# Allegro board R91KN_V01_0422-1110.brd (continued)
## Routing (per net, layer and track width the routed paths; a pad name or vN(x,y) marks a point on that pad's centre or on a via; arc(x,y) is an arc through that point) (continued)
+3.3V_DPB:
  vias: v3(13.55,88.3) v3(13.9,90.9) v3(14.45,88.4) v3(14.65,90.9)
+5V: length 43.7
  TOP w1: v2(36.37,40.31) 43.96,47.9 v2(43.97,47.9) ; v2(48.49,30.4) 42.55,30.4 v2(42.52,30.38) 40.24,28.1 R4413.1
  BOTTOM w1: v2(36.37,40.31) 36.37,36.53 v2(42.52,30.38) ; U861.4 50.18,26.49 48.76,26.49 C868.1 48.08,26.71 47.2,27.58 47.2,29.12 v2(48.49,30.4) 48.54,30.45 48.54,30.5 48.55,30.51 R866.1
+5V_HDMI: length 48.9
  TOP w0.3: C2722.1 16.06,60.7 13.02,60.7 11.73,59.41 MJ2501.18
  TOP w0.5: v3(19.85,61.54) 18.89,61.54 17.95,60.6 17.35,60.6 16.96,60.21 C2722.1 ; v3(19.85,60.24) R2701.1
  TOP w0.7: v3(19.85,61.54) R2703.1
  L3_INNER w1: v3(35.35,33.7) 35.35,36.9 22.86,49.39 22.86,57.23 v3(19.85,60.24) v3(19.85,61.54)
  BOTTOM w0.7: MR2721.2 34.88,34.17 v3(35.35,33.7)
+5V_VESA: length 57.6
  TOP w0.7: v3(18.18,22.5) R1005.1 17.34,22.09 ; R1008.1 v3(18.21,23.8)
  TOP w1: v3(13.85,21.4) 14.05,21.2 16.45,21.2 17.34,22.09 ; R4412.1 37.94,27.51 v3(37.95,27.5)
  L3_INNER w1: v3(18.18,22.5) 18.21,22.53 v3(18.21,23.8) 19.35,24.94 19.35,29.2 20.84,30.69 v3(20.84,32.51)
  BOTTOM w0.2: 10.46,23.88 9.52,24.82 7.75,24.82 6.84,23.91 J1601.14 7.82,22.91 9.5,22.91 10.46,23.88
  BOTTOM w0.7: 32,31.2 32.4,31.59 U1999.14 33.17,32.87
  BOTTOM w1: v3(13.85,21.4) 13.85,23.73 12.85,24.73 11.31,24.73 10.46,23.88 ; 33.17,32.87 R2014.1 33.47,33.17 R2721.1 34.58,32.77 37.95,29.4 v3(37.95,27.5) ; v3(20.84,32.51) C1624.1 26.13,32.51 C1999.2 26.8,32.55 28.15,31.2 32,31.2
+5V_VESA2: length 14.8
  TOP w1: R4411.1 v3(42.54,28.11)
  BOTTOM w0.5: 34.56,35.13 MR2721.1
  BOTTOM w0.7: MR2721.1 35.5,35.15 ; MR2014.1 34.56,35.13
  BOTTOM w1: 35.5,35.15 v3(42.54,28.11)
+5V_VGAH: length 95.1
  TOP w0.5: v3(19.04,91.49) R2008.1 ; 9.21,93.32 C1011.1 ; R2005.1 19.04,89.39 v3(18.45,88.8)
  TOP w1: 9.21,93.32 9.7,93.81 9.7,98.55 10.85,99.7 13.75,99.7 19.04,94.41 v3(19.04,91.49)
  L3_INNER w1: MJ1001.9 5.58,85.17 7.45,83.3 7.45,74.7 9.05,73.1 9.05,72.1 10.25,70.9 15.35,70.9 17.55,68.7 17.55,50.89 31.63,36.81 31.63,36.42 v3(32.25,35.8)
  BOTTOM w0.7: 32.25,34.69 32.8,34.15 MR2014.2
  BOTTOM w1: v3(18.45,88.8) 19.04,89.39 v3(19.04,91.49) ; v3(32.25,35.8) 32.25,34.69
  vias: v3(6.1,92.35) v3(7.25,92.4) v3(8.38,92.33)
+12V_BUS: length 52.4
  TOP w0.5: MPCIE1.B1 45.65,5.8 v2(46.85,7) ; C43.1 v3(114.55,107.9) ; v3(26.85,84.2) 31.44,84.2 R1805.1 ; R844.1 19.12,48.49 20.85,46.76 24.11,46.76 v3(27.45,50.1) ; C47.1 v3(152.05,105.1) ; R843.2 v3(150.95,105.1) ; R4055.2 v3(111.52,107.87) ; C44.1 v3(108.03,107.12) ; R4105.1 v3(156.75,30.9)
  TOP w0.8: D701.2 151.47,96.9 C706.1 152.06,97.11 v2(152.95,98) ; R707.1 v2(149.95,106.81) ; R607.1 65.61,96.44 65.15,96.9 v2(63.65,96.9) ; D601.2 59.96,106.33 C606.1 59.96,107.82 v2(60.68,108.53)
  BOTTOM w0.5: R1804.1 26.21,86.51 v3(26.59,86.89) ; R857.1 R852.2 v3(21.38,84.27)
  BOTTOM w0.8: v2(63.65,96.9) 62.51,96.9 58.9,100.51 58.9,104.04 v2(57.05,105.89)
  vias: v2(21.15,99.1) v2(21.15,97.5) v2(21.15,96.1) v2(21.35,104.6) v2(21.35,103.1) v2(25.25,106) v2(26.55,106.1) v2(46.75,11.6) v2(46.75,10.3) v2(46.75,9) v2(48.05,11.6) v2(48.05,10.3) v2(48.05,9) v2(48.05,7.7) v2(49.35,11.6) v2(49.35,10.3) v2(49.35,9) v2(50.65,11.6) v2(50.65,10.3) v2(50.65,9) v2(129.95,103.3) v2(131.15,103.3) v2(132.35,103.3) v3(160.55,31.1) v3(160.55,30.3) v3(161.45,31.1) v3(161.45,30.3)
+AVDD: length 4.2
  TOP w0.3: v1(81.35,52.65) 81.4,52.65 U1.AG24
  BOTTOM w0.4: C1054.1 80.29,51.67 C1055.1 79.27,51.02 78.79,50.53 B2.2
  BOTTOM w0.5: v1(81.35,52.65) 81.16,52.65 80.29,51.78 C1054.1
+VCCT_DAC: length 3.7
  TOP w0.25: U4050.13 64.36,89.45 63.99,89.45 63.77,89.23 63.27,89.23 R4075.2 ; C4070.1 62.54,89.99 63.26,89.27 R4075.2 ; C4071.1 R4075.2
+VDD1DI: length 12.9
  TOP w0.2: v3(77.85,53.14) 78.13,53.42 78.13,53.42 78.22,53.52 79.06,53.52 79.16,53.42 80.87,53.42 81.4,53.94 81.4,53.95 81.6,54.15 81.61,54.15 82.85,54.15 83.21,53.8 U1.AE23
  BOTTOM w0.4: v3(77.85,53.14) 78.54,53.83 78.9,53.83 79.32,53.41 C1052.1
  BOTTOM w0.5: v3(77.85,53.14) 76.28,53.14 C1050.1 76.14,51.89 B6.2 ; C1051.1 80.28,53.35 C1052.1
+VDDC: length 284.5
  TOP w0.3: U1.T12 89.75,61.6 U1.U13 89.75,61.3 v1(90.15,60.9) 90.55,60.5 U1.T15 v1(91.05,59.9) U1.R16 91.63,59.4 v1(92.04,59) 92.43,58.6 U1.N17 92.55,58.5 v1(92.97,58.08) ; U1.T12 90.55,62.38 v1(91.07,61.85) 91.1,61.85 U1.R13 91.55,61.34 v1(92.04,60.84) 92.48,60.4 U1.N15 ; U1.T12 90.55,62.52 v1(90.16,62.91) ; v1(92.97,59.87) 93.44,59.4 U1.M16 ; v1(92.97,59.87) 93.5,60.4 U1.M15 ; v1(92.97,59.87) 92.55,60.29 U1.N15 ; U1.N15 92.55,60.42 v1(93.09,60.97) 93.53,61.4 U1.M13 ; v1(87.24,61) 86.75,60.51 U1.AA15 U1.Y16 87.84,59.4 v1(88.25,58.99) 88.64,58.6 U1.V17 v1(89.25,58.1) U1.U18 89.75,57.5 v1(90.15,57.1) 90.55,56.7 U1.T20 90.55,56.55 91,56.1 91.05,56.1 U1.R21 ; 88.25,57.1 88.25,57.09 U1.Y18 ; 88.25,57.1 v1(88.25,57.16) ; 88.25,57.1 88.75,56.6 U1.V20 88.75,56.58 89.72,55.6 U1.U21 ; U1.Y21 87.75,55.65 NS600.1 88.72,55.6 U1.V21 ; U1.Y13 v3(88.25,60.9) U1.V15 v3(89.25,59.9) U1.U16 U1.T17 v1(91.05,58.1) U1.R18 91.55,57.55 v1(92,57.1) 92.5,56.6 U1.N20 92.56,56.6 v1(93.02,57.06) ; v1(93.02,57.06) 93.47,56.6 U1.M20 U1.M21 ; v1(93.02,57.06) 93.55,57.59 U1.M18 93.45,57.6 v1(92.97,58.08) ; v1(92.97,58.08) 93.5,58.6 U1.M17
  TOP w0.4: U1.M13 U1.M12 v1(93.05,62.9) U1.M11
  TOP w0.5: R841.1 143.62,105.45 v3(143.62,104.74)
  TOP w0.503: 53.54,89.9 L601.2 ; L601.2 52.11,90.43 ; L601.2 51.59,91.86 ; L601.2 53.54,93.81 ; L601.2 52.11,93.29 ; L601.2 54.97,93.29 ; L601.2 54.97,90.43 ; L601.2 55.49,91.86 ; C626.1 53.15,87.24 ; C626.1 53.15,86.68 ; C626.1 52.02,87.24 ; C626.1 53.15,86.11 ; C626.1 50.89,85.55 ; C626.1 52.58,87.24 ; C626.1 50.89,86.11 ; C626.1 50.89,87.24 ; C625.1 44.4,87.24 ; C625.1 44.96,87.24 ; C625.1 45.53,86.68 ; C625.1 45.53,86.11 ; C625.1 43.27,85.55 ; C625.1 43.27,86.11 ; C625.1 43.27,87.24 ; C625.1 45.53,87.24
  L3_INNER w0.5: NS600.1 89.1,56.11
  L3_INNER w0.603: 43.32,86.11 C625.1 ; C625.1 45.48,86.11 ; C625.1 44.4,87.19 ; C625.1 43.59,86.92 ; C625.1 45.21,85.3 ; C625.1 43.59,85.3 ; C625.1 44.4,85.04 ; C625.1 45.21,86.92 ; L601.2 53.54,93.76 ; L601.2 54.94,93.25 ; L601.2 53.54,89.95 ; L601.2 51.64,91.86 ; L601.2 54.94,90.46 ; L601.2 52.15,93.25 ; L601.2 55.44,91.86 ; L601.2 52.15,90.46 ; C626.1 52.83,86.92 ; C626.1 51.21,85.3 ; C626.1 52.02,85.04 ; C626.1 52.83,85.3 ; C626.1 51.21,86.92 ; C626.1 53.1,86.11 ; C626.1 52.02,87.19 ; C626.1 50.94,86.11
  BOTTOM w0.2: C172.1 94.57,56.58 C193.1
  BOTTOM w0.3: v1(90.16,62.91) 90.64,62.43 C190.1 ; v3(95.05,71.98) 95.05,71.3 95.67,70.68 95.67,70.12 MB9.1 ; C184.1 94.5,59.36 93.67,59.36 C189.1 93.45,59.35 93.1,59.01 v1(93.06,59.01) ; C195.1 91.57,61.31 v1(92.04,60.84) 92.26,60.84 C87.1 ; 87.29,59.99 C174.1 87.19,60.95 v1(87.24,61) ; 87.29,59.99 MC174.1 87.34,59.99 v3(88.25,60.9) ; 87.29,59.99 88.25,59.02 v1(88.25,58.99) 89.14,58.1 v1(89.25,58.1) 90.15,57.2 v1(90.15,57.1) ; C87.1 92.62,60.22 v1(92.97,59.87) 93.57,60.47 C86.1 93.57,60.49 v1(93.09,60.97) 92.62,60.49 C87.1 ; v3(88.25,60.9) v3(89.25,59.9) v1(91.05,58.1) ; v3(88.25,60.9) 88.25,60.93 C168.1 87.58,62.27 C173.1 ; C85.1 92.47,63.48 v1(93.05,62.9) 93.32,62.9 93.6,63.18 C188.1 ; v1(91.07,61.85) 91.07,61.88 90.78,61.58 C187.1 90.39,61.14 v1(90.15,60.9) 90.15,60.8 v1(91.05,59.9) 91.93,59.02 v1(92.04,59)
  BOTTOM w0.4: v1(92,57.1) 92.44,57.55 C194.1 ; C170.1 86.2,74.12 v3(86.23,74.09) ; MC176.1 90.23,56.12 90.23,57.02 v1(90.15,57.1) ; C189.1 93.16,59.87 v1(92.97,59.87) 92.91,59.87 v1(92.04,59) 92.96,58.08 v1(92.97,58.08) 92.54,57.64 C194.1 ; C183.1 87.69,58.82 88.08,58.82 v1(88.25,58.99) ; C194.1 92.54,57.54 v1(93.02,57.06) 93.49,56.58 C193.1 ; C169.1 88.74,56.68 v1(88.25,57.16) 87.7,56.61 C185.1 ; C195.1 91.56,61.37 v1(91.07,61.85) 90.66,62.27 C190.1
  BOTTOM w0.5: v3(75.72,71.91) 75.71,71.92 C171.1 ; v3(83.62,80.24) 83.62,79.48 83.29,79.15 C196.1 82.68,79.5 v3(82.68,80.34) ; C175.1 73.54,80.41 C186.1 ; C175.1 MC175.1 74.33,80 74.83,79.5 v3(75.49,79.5) ; C175.1 v3(75.62,80.41) ; v3(62.43,94.28) 63.58,95.43 70.18,95.43 73.05,98.3 82.65,98.3 87.85,103.5 117.04,103.5 118.28,104.74 138.51,104.74 139.85,103.4 142.28,103.4 v3(143.62,104.74)
  BOTTOM w0.503: 43.27,86.11 C625.1 ; C625.1 43.27,84.99 ; C625.1 45.53,84.99 ; C625.1 44.4,87.24 ; C625.1 43.27,87.24 ; C625.1 45.53,87.24 ; C625.1 45.53,86.11 ; C625.1 44.4,84.99 ; 52.11,93.29 L601.2 ; L601.2 55.49,91.86 ; L601.2 53.54,89.9 ; L601.2 51.59,91.86 ; L601.2 54.97,93.29 ; L601.2 54.97,90.43 ; L601.2 53.54,93.81 ; L601.2 52.11,90.43 ; 50.89,86.11 C626.1 ; C626.1 53.15,87.24 ; C626.1 53.15,84.99 ; C626.1 52.02,87.24 ; C626.1 53.15,86.11 ; C626.1 52.02,84.99 ; C626.1 50.89,87.24 ; C626.1 50.89,84.99
  vias: v2(44.96,90.68) v2(44.96,88.39) v2(45.72,91.82) v2(45.72,89.53) v2(46.48,90.68) v2(46.48,88.39) v2(46.48,86.11) v2(47.24,91.82) v2(47.24,89.53) v2(47.24,87.25) v2(48.01,90.68) v2(48.01,88.39) v2(48.01,86.11) v2(48.77,91.82) v2(48.77,89.53) v2(48.77,87.25) v2(49.53,90.68) v2(49.53,88.39) v2(49.53,86.11) v2(50.29,91.82) v2(50.29,89.53) v2(50.29,87.25) v2(51.05,90.68) v2(51.05,88.39) v2(51.82,89.53) v2(52.58,88.39) v2(54.1,88.39) v2(54.1,86.11) v2(54.86,89.53) v2(54.86,87.25) v2(55.63,90.68) v2(55.63,88.39) v2(55.63,86.11) v2(56.39,89.53) v2(56.39,87.25) v3(52.15,69.1) v3(53.05,69.1) v3(53.95,69.1) v3(54.85,69.1)
+VDDC_SOURCE: length 11.5
  TOP w0.503: 38.27,95.74 C631.1 ; C631.1 39.52,93.24 ; C631.1 38.27,93.24 ; C631.1 39.52,95.74 ; C631.1 40.14,95.74 ; C631.1 38.27,93.86 ; C631.1 38.89,93.24 ; C631.1 38.27,94.49
GND: length 1641.2
  TOP w0.097: v1(139.43,49.27) 138.97,48.81 U202.T1
  TOP w0.1: v3(27.05,18.9) 27.05,20.5 30.4,23.85 30.4,26.5 v3(32.4,28.5) 48.88,44.98 v3(70.65,44.98) ; v3(25.45,26.4) 25.45,27.89 47.24,49.68 72.72,49.68 v3(72.99,49.96) ; v3(70.45,34) 71.75,35.3 71.75,40.15 76.53,44.93 v3(76.53,45.3) ; v3(78.9,47.62) 78.9,45.25 v1(78.08,44.42) 77.65,44.42 72.95,39.73 72.95,33.4 v3(71.95,32.4) ; 132.56,69.38 132.46,69.38 132.46,69.37
  TOP w0.2: v1(137.76,78.58) 137.77,78.58 138.33,78.58 138.72,78.97 U401.B9 ; v1(132.12,79.34) 132.5,78.97 132.56,78.97 ; 125.38,58.13 125.46,58.05 125.46,55.7 124.98,55.23 124.98,51.64 v1(125.22,51.41) ; 125.38,58.13 125.45,58.13 126.3,58.98 126.3,61.23 125.22,62.31 125.22,62.31 v1(125.22,62.31) ; 125.38,58.13 125.28,58.23 120.72,58.23 120.62,58.13 ; 133.37,73.38 133.12,73.38 132.71,72.97 132.03,72.97 131.94,72.88 131.82,72.88 131.51,72.58 v3(131.41,72.58) ; v1(136.88,76.17) 137.52,76.17 137.92,76.58 U401.E8 ; 132.56,37.62 132.81,37.62 133.2,38.01 133.76,38.01 v1(133.76,38.02) ; v1(139.5,38.92) 139.5,38.93 139.5,38.94 139.22,39.22 138.97,39.22 ; 138.97,37.62 139.06,37.52 139.61,37.52 v1(139.72,37.41) ; v1(95.17,70.47) 95.17,70.44 95.35,70.26 U1.K2 ; v1(101.85,67.7) 101.84,67.69 101.59,67.69 101.3,67.4 101.1,67.4 101.09,67.4 U1.B6 ; U1.AG14 82.11,61.37 82.11,62.06 81.84,62.34 81.84,62.35 81.75,62.44 U1.AG12 ; 120.62,58.13 120.62,58.16 120.2,58.59 120.2,60.03 121.19,61.02 121.19,62.28 121.02,62.46 v3(120.84,62.46) 120.84,62.56 120.81,62.59 120.81,62.76 121.47,63.42 122.02,63.42 v3(122.26,63.66) ; 120.62,58.13 120.62,56.58 121.68,55.53 121.68,50.79 121.77,50.7 v1(121.8,50.7) ; v1(78.56,67.43) 78.58,67.4 U1.AM6 ; U1.B16 101.62,59.4 ; v1(101.69,65.93) 101.63,65.86 101.31,65.8 U1.B8 ; v1(99.75,50.2) U1.E28 ; v1(134.66,40.41) 134.01,40.41 133.68,40.09 133.57,40.09 133.5,40.02 133.37,40.02 ; U1.F12 98.72,62.77 v1(99.2,62.77) ; J2501.19 15.23,86.38 15.57,86.72 16.05,86.72
  TOP w0.22: v1(101.66,56.2) U1.B20 ; U1.B18 101.57,57.8 101.58,57.81 v1(101.6,57.81) ; U1.B22 v1(101.65,54.6) ; v1(101.55,62.64) 101.53,62.62 U1.B12 ; v1(101.64,59.44) 101.64,59.41 101.62,59.4 ; 100.59,61 100.6,61.01 100.61,61.02 101.86,61.02 v1(101.88,61.04)
  TOP w0.23: 95.55,46.61 95.25,46.91 95.25,48.1 U1.K32 ; v1(98.67,70.16) 98.67,70.15 98.62,70.1 98.62,69.47 U1.F2
  TOP w0.25: v1(78.75,65.91) 78.76,65.91 78.87,65.8 U1.AM8 ; U1.AG12 81.8,62.65 81.8,62.75 81.84,62.79 81.84,63.31 U1.AG11 ; U1.J31 96.15,47.96 v1(96.27,47.84) ; v1(81.35,70.5) 81.75,70.1 U1.AG1 ; 132.56,48.84 132.56,48.81 ; U1.B14 100.59,61 ; v1(101.88,69.87) 101.02,69 U1.A3 ; U4050.3 68.12,89.84 v3(68.22,89.94) ; v1(137.76,73.77) 137.93,73.6 137.94,73.6 U401.J8 ; v3(83.35,71.09) U1.AE1 U1.AE3 ; U1.B10 100.61,64.2 100.62,64.2 101.58,64.2 v1(101.65,64.27) ; v1(101.65,52.99) 101.64,53 U1.B24 ; 81.36,61.39 U1.AG14 ; v1(97.79,47.6) 97.75,47.64 U1.G31 ; U1.H2 96.95,70.41 96.91,70.44 v1(96.91,70.46) ; v1(99.2,59.38) 99.19,59.4 U1.F16 ; 132.56,67.75 132.56,67.78 ; U1.F18 98.41,57.66 97.48,57.66 v1(97.35,57.8) ; v1(138.56,43.61) 138.16,43.22 ; v1(101.65,51.4) 101.64,51.4 101.3,51.4 101.29,51.41 100.61,51.41 100.6,51.4 U1.B26
  TOP w0.3: v1(84.47,57.81) 84.47,57.69 U1.AC19 ; U1.P25 91.97,52.2 92.3,52.52 92.55,52.52 ; v1(95.35,68) U1.K6 U1.J7 U1.H6 96.95,68.05 v3(96.95,68.05) ; v1(95.75,51.05) 96.15,50.65 U1.J27 ; U1.L27 94.55,50.15 v1(94.8,49.9) 94.9,49.8 U1.K28 ; U1.AG27 81.67,50.6 81.44,50.83 v1(81.25,50.85) ; v1(82.15,53.41) 82.16,53.4 83.75,53.4 U1.AD23 ; v1(82.15,53.41) 82.15,53.46 82.49,53.8 U1.AF23 ; v1(82.15,53.41) 81.76,53.8 U1.AG23 ; v1(131.85,71.1) 131.95,71.1 132.07,70.97 132.56,70.97 ; U401.D8 U401.E8 ; U1.N11 U1.R11 ; U1.H20 96.95,56.28 97.25,56.58 v1(97.25,56.6) ; U1.AD25 v1(84.55,51.8) U1.AC26 85.06,51.29 85.06,50.71 U1.AC27 ; v1(136.97,38.01) 136.98,38.01 137,38 137.04,38 137.37,37.67 137.37,37.62 ; U1.T6 90.55,67.31 90.23,66.99 90.23,66.98 v1(90.23,66.98) ; U1.H14 96.95,60.87 97.5,61.42 v1(98.05,61.42) 98.14,61.42 98.55,61.02 U1.F14 ; v1(137.78,39.61) 138.16,40 U202.E2 ; U4001.6 v3(76.65,94.08) ; U1.Y10 87.14,64.19 v1(86.56,64.19) 85.95,64.19 U1.AB10 ; MJ2501.11 v3(8.37,55.91) ; U1.AB24 85.67,53.27 85.45,53.27 v1(85.42,53.25) 85.2,53.25 U1.AC24 ; v1(132.96,77.78) 132.94,77.78 132.56,77.41 132.56,77.38 ; v3(87.7,51.8) 87.7,51.75 88.05,51.4 U1.W26 88.35,50.8 U1.W27 ; v3(87.7,51.8) 87.9,51.8 88.3,52.2 U1.W25 88.4,52.2 v1(88.95,52.75) ; v3(87.7,51.8) 87.4,52.1 87.25,52.1 U1.Y25 ; U1.AH5 81.34,67.81 v1(81.4,67.8) 81.35,67.8 U1.AG6 ; 132.56,47.22 132.03,47.22 v1(131.97,47.27) ; U1.F6 98.81,67.14 99.07,67.14 99.07,67.15 v1(99.07,67.15) ; 103.45,34.99 v1(104.84,33.6) 105.51,32.92 106.07,32.92 106.08,32.92 106.21,32.92 107.54,31.59 110.07,31.59 110.19,31.48 v1(113.85,31.48) v3(116.19,31.48) v1(120.66,31.48) 121.23,31.48 121.62,31.22 121.77,31.13 123.04,29.86 123.27,29.86 v1(123.57,29.56) 123.83,29.3 136.56,29.3 v3(142.05,34.8) ; 103.45,34.99 v3(103.46,34.99) ; 103.45,34.99 103.45,35 v1(101.32,37.13) 99.81,38.65 99.81,41.08 99.06,41.89 95.55,45.4 v1(95.55,46.38) 95.55,46.61 ; U1.AM32 78.9,47.75 v3(78.9,47.62) ; v1(101.52,48.73) 101.25,49 U1.A30 ; U1.Y17 87.72,58.6 v1(87.28,58.16) ; U1.Y17 87.79,58.6 v1(88.25,58.14) 88.75,57.64 U1.V18 v1(89.25,57.1) U1.U20 90.55,55.8 U1.T21 90.55,55.52 v1(91.05,55.02) ; U1.Y17 86.95,59.4 U1.AA16 U1.AB15 ; v1(132,69.33) 132,69.34 132.04,69.34 132.07,69.37 132.46,69.37 ; 92.55,52.52 92.82,52.52 U1.N25 ; 92.55,52.52 v1(92.55,52.5) ; v1(89.03,47.6) 89.03,48.12 U1.V32 ; U1.N16 v1(92.05,59.9) U1.R15 v1(91.05,60.9) U1.T13 ; v1(92.12,68.07) 92.15,67.89 U1.P6 ; v1(100.58,70.3) 100.48,70.2 100.48,70.1 100.26,69.87 100.22,69.87 U1.C1 ; U1.G8 97.75,65.85 97.84,65.94 97.95,65.94 97.96,65.94 98.37,65.94 98.38,65.94 98.41,65.94 U1.F8 v3(99.15,65.8) ; v1(98.96,64.6) 98.56,64.2 U1.F10 ; v1(91.25,49.95) 91.35,50.05 U1.R27 ; R214.2 127.61,73.25 127.25,73.25 127.19,73.18 v3(127.18,73.18) ; 132.56,48.84 132.37,49.05 v1(132.37,49.34) ; U1.AG9 81.36,64.61 v1(81.33,64.61) 81.33,64.56 80.97,64.2 U1.AH10 ; v1(82.32,47.52) 82.32,47.97 U1.AF32 ; U1.N27 93.05,50.5 93.05,50.05 v1(92.95,49.95) ; U1.W1 88.15,70.26 v1(88.09,70.32) ; v1(132.97,43.62) 132.97,43.62 133.37,43.23 133.37,43.22 ; U1.AF19 82.17,56.82 v1(82.17,56.64) 82.17,56.38 U1.AF20 83.03,55.52 83.03,55.2 83.03,55.19 83.03,55.12 U1.AE22 ; v3(130.56,77.2) 130.66,77.11 130.97,77.11 131,77.08 131.12,77.08 131.56,76.64 131.62,76.64 131.63,76.63 131.98,76.63 132.04,76.58 133.37,76.58 ; v1(80.58,49.42) 80.95,49.8 U1.AH28 ; 91.03,57.12 U1.T18 90.55,57.7 v1(90.15,58.1) 89.75,58.5 U1.U17 89.65,58.6 v1(89.25,59) 88.85,59.4 U1.V16 88.75,59.48 v3(88.33,59.9) 87.83,60.4 U1.Y15 ; 91.03,57.12 v1(91.03,57.15) ; 91.03,57.12 U1.R20 U1.N21 92.62,55.6 93.02,55.99 v1(93.02,56.05) ; U1.AM18 79.31,57.76 78.8,57.76 v1(78.6,57.56) ; J2501.2 v3(11.95,77.88) ; U1.F26 v1(98.15,51) U1.G27 97.75,50.6 v1(98.15,50.2) ; v1(78.71,59.36) 78.79,59.4 U1.AM16 ; 133.37,39.22 133.2,39.38 133.2,39.71 133.25,39.76 133.25,39.9 133.37,40.02 ; U1.AM1 79.19,69.8 v1(78.81,70.18) ; U1.AC9 84.99,65 v1(85.45,65.46) ; U1.H17 97.17,58.17 97.17,57.98 v1(97.35,57.8) ; MJ2501.2 v3(8.34,51.41) ; v3(77.87,56.98) 78.57,56.98 U1.AM20 ; MJ2501.17 v3(12.06,58.91) ; v1(134.56,78.58) U401.B3 ; C377.2 142.49,55.17 v3(142.7,55.38) ; v3(78.29,61) 78.42,60.87 79.19,60.87 79.31,61 U1.AM14 ; v1(139.53,41.59) 139.5,41.59 139.47,41.62 138.97,41.62 ; 132.56,67.75 132.35,67.53 132.35,67.25 v1(132.33,67.23) ; 138.97,47.22 v1(139.56,47.22) ; U1.M6 93.75,67.83 v1(93.91,68) ; U1.P9 91.95,65.14 92.42,65.61 92.42,65.67 v1(92.57,65.82) ; U1.AM24 79.33,52.98 78.58,52.98 78.53,53.02 v1(78.53,53.03) ; R206.2 143.96,68.9 v3(144.18,69.12) ; 132.56,45.62 131.89,45.62 v1(131.84,45.56) ; U1.A32 100.97,48.2 101.39,47.77 v3(101.47,47.77) ; U1.K11 v1(95.35,62.6) ; J2501.11 v3(11.95,82.38) ; v1(131.5,40.88) 131.56,40.81 132.56,40.81 ; 132.56,36.81 132.56,36.73 132.34,36.51 132.34,36.34 132.3,36.29 v1(132.3,36.27) ; U1.AB32 v1(85.75,47.55) ; U1.AD32 v1(84.15,47.55) ; U1.U27 89.75,50.8 90.1,51.15 90.1,51.7 ; U1.V13 v3(89.25,60.9) U1.U15 89.75,60.3 v1(90.15,59.9) 90.55,59.5 U1.T16 90.65,59.4 v1(91.05,59) 91.45,58.6 U1.R17 v1(92.05,58.1) U1.N18 ; v1(139.76,39.74) 139.75,39.74 139.73,39.72 139.56,39.72 139.26,40.02 U202.E1 ; v1(97.31,63.81) 97.36,63.81 U1.G10 ; v1(88.93,64.92) 89.04,65.03 89.53,65.03 U1.U9 ; U401.A9 138.97,79.98 139.29,80.31 139.29,80.42 v1(139.39,80.52) ; U1.AA27 86.2,50.25 v3(86.2,50.15) ; v1(87.25,57.19) 87.75,56.69 U1.Y20 ; U1.AH8 80.95,65.8 81.3,66.15 v1(81.4,66.2) 81.39,66.24 81.4,66.25 81.43,66.25 81.7,66.52 81.7,66.55 U1.AG7 ; U1.C32 100.15,47.87 v1(100.51,47.51) ; J2501.16 v3(11.97,84.88) ; 138.97,45.62 v1(139.59,45.62) ; v1(99.15,54.6) U1.F22 ; v1(80.58,48.6) 80.95,48.23 U1.AH32 ; J2501.5 v3(11.93,79.38) ; U1.AF10 82.56,64.2 v1(83.03,63.73) ; U1.U3 89.75,69.01 89.72,69.04 89.72,69.75 89.75,69.78 U1.U1 89.77,69.81 89.77,70.89 v1(89.94,71.07) ; U1.AD6 84.1,67.4 v1(83.7,67) 83.35,66.65 U1.AE7 ; U1.AE27 83.31,50.56 v1(83.31,50.06) ; U1.AA1 v1(86.55,70.4) ; U1.V6 88.9,67.4 v1(88.54,67.76) 88.36,67.76 88.32,67.8 87.75,67.8 U1.Y6 ; U1.F24 98.72,52.83 98.97,52.83 v3(99.2,53.06) ; 90.1,51.7 90.1,51.8 90.5,52.2 U1.T25 90.2,52.75 v1(90.15,52.75) 90.1,52.75 U1.U25 90.05,51.7 90.1,51.7 ; U1.P32 92.18,48.17 92.18,47.58 v1(92.14,47.54) ; U1.Y32 v1(87.35,47.5) ; v1(90.65,47.55) 90.55,47.65 U1.T32 ; U401.M9 139.4,70.97 v1(139.55,71.13) ; v1(119.17,49.71) 118.84,50.04 C332.1 ; v1(78.45,54.6) U1.AM22 ; v3(98.42,77.97) 98.59,77.97 99.01,78.4 99.03,78.43 99.15,78.54 99.15,78.9 100.82,80.58 v3(100.92,80.58) 101.16,80.58 101.16,80.61 v3(104.76,84.2) 107,86.44 v3(107.1,86.44) 107.53,86.87 136.78,86.87 142.41,81.24 v3(142.41,81.17) ; J2501.8 v3(11.95,80.88) ; v1(131.97,41.65) 132,41.62 133.37,41.62 ; U1.AB6 v1(85.75,68.07) ; U1.M32 v1(93.75,47.58) ; MJ2501.8 v3(8.37,54.41) ; U401.P9 v1(139.56,69.38) ; v3(139.99,75.78) 139.97,75.78 139.96,75.78 U401.F9 ; v3(139.56,74.97) U401.G9 ; 132.56,74.97 v1(131.76,74.97) ; MJ2501.5 v3(8.35,52.91) ; U4.3 v3(57.8,14.05)
  TOP w0.4: C328.1 120.53,73.45 v1(120.17,73.81) ; R218.2 127.57,44.7 127.41,44.87 127.38,44.87 v1(127.38,44.87) 127.38,45.19 127.79,45.6 C438.2 R204.2 127.69,46.5 v3(127.23,46.97) 127.1,47.09 127.1,47.23 126.71,47.63 C122.2 ; v3(144.22,71.17) 143.64,71.17 R219.2 ; D1602.3 D1602.8 v3(15.32,40.39) ; C351.1 116.91,81.56 v1(117.37,82.03) ; v3(11.45,16.52) 11.45,16.52 11.59,16.36 12.25,16.36 ; C358.2 121.53,65.37 v1(121.59,65.31) ; v3(18.05,80.1) D4402.3 D4402.8 ; v3(11.31,17.5) 11.6,17.8 11.67,17.8 D1002.2 ; v3(18.15,76.1) D4401.3 D4401.8 ; C353.1 120.31,65.29 120.55,65.06 120.62,65.06 120.63,65.05 v1(120.63,65.05) ; C301.1 143.44,71.94 144.19,71.94 v3(144.2,71.94) ; R217.2 v3(144.34,44.9) ; D1603.3 D1603.8 v3(11.96,31.24) ; C343.1 127.97,71.36 127.6,71.72 127.53,71.72 v3(127.45,71.8) ; v3(143.51,58.75) 143.31,58.55 MC369.2 141.41,58.55 v3(141.06,58.9) ; C362.2 143.69,73.94 144,74.25 v1(144.28,74.25) ; C125.2 125.02,65.07 125.1,65.07 125.18,65.14 125.18,65.2 v1(125.19,65.2) ; C312.1 v1(127.78,40.1) ; C463.2 143.85,70 v3(144.25,70.4) ; R710.2 v3(143.09,101.98) ; v3(126.68,79.38) 127.2,78.85 127.31,78.85 ; v3(127.75,39.15) 127.74,39.15 127.74,39.16 127.75,39.15 127.86,39.15 127.91,39.1 C311.1 ; v3(16.46,51.7) D2504.8 D2504.3 ; v3(144.28,43.22) 144.16,43.1 R212.2 ; C365.2 143.24,62.4 v3(142.26,61.42) ; 127.31,78.85 C383.2 MC383.2 ; 127.31,78.85 v3(126.59,78.14) ; MR57.2 v3(76.97,83.53) ; C499.2 127.65,48.49 127.68,48.49 127.91,48.27 128.12,48.27 v3(128.3,48.09) ; v1(86.28,60.91) 86.75,61.39 U1.AA13 ; C315.1 115.93,49.76 v1(115.89,49.72) ; v1(94.9,54.07) 94.91,54.07 94.91,54.06 94.92,54.06 94.92,54.06 94.93,54.06 94.93,54.05 94.93,54.05 94.93,54.05 95.35,54.47 U1.K22 ; v3(14.91,26.33) D1601.8 D1601.3 ; U1.T11 90.66,63.4 v1(91.13,62.92) ; C373.2 139.89,86.33 v3(139.89,85.7) ; v3(61.67,92.56) 62.14,92.09 C4070.2 v3(62.54,93.17) ; v3(141.85,51) 142.23,51.38 MC366.2 ; C126.2 140.25,58.32 v3(140.2,58.37) ; v1(113.1,62.02) 113.08,62 C371.2 ; v1(91.13,62.92) 91.55,63.34 U1.R11 ; v1(91.13,62.92) 91.55,62.51 U1.R12 91.56,62.4 v1(92.06,61.89) ; v1(138.54,60.54) 138.94,60.15 C355.2 ; v3(144.34,46.52) 143.51,46.52 143.44,46.59 R202.2 ; v1(84.47,57.81) 84.49,57.84 84.49,57.94 U1.AC17 ; v1(99.01,55.88) 98.9,55.88 98.88,55.9 98.85,55.9 U1.F20 ; C330.1 v1(121.62,47.6) ; U1.N13 92.55,61.41 v1(92.06,61.89) ; v1(136.14,59.91) 136.32,59.73 C356.2 ; U1.AH14 80.97,61 81.36,61.39 81.36,61.38 v3(81.35,61.38) ; C334.1 100.48,43.65 v3(100.59,43.77) 100.84,44.02 v1(100.84,45.02) ; C305.1 144.25,77.6 144.45,77.4 v3(144.45,77.35) ; D1600.8 D1600.3 v3(11.91,35.05) ; C300.1 127.05,68 126.75,68.31 126.75,68.64 v3(126.7,68.69) ; C413.2 143.52,45.72 v3(144.31,45.72) ; v1(125.82,37.02) 127.18,37.02 C364.2 127.12,36.35 v1(126.44,36.35) ; v1(60.85,89.5) 62.03,88.32 C4071.2 ; v1(92.06,61.89) 92.55,62.38 U1.N12 ; D2503.3 D2503.8 v3(16.52,56.1) ; C363.2 143.53,72.94 144.09,73.49 v3(144.23,73.49) ; v1(83.49,61.37) 83.5,61.35 83.5,60.95 U1.AE14 ; C142.2 127.34,27.77 v1(127.81,27.31) ; MPCIE1.B60 106.65,6.2 106.15,6.7 v1(106.05,6.7) ; Q840.2 v3(141.19,104.66) ; v3(143.39,66.29) 143.39,67.02 C354.1 ; C337.1 143.86,75.02 v3(144.55,75.02) ; C309.1 143.73,40.91 v3(144.24,40.91) ; U1.AC9 U1.AD8 ; C500.2 v3(127.53,66.05) ; C307.1 v3(144.25,38.9) ; U1.AF19 U1.AE19 ; C342.1 144.32,76.7 v3(144.45,76.58) ; C310.1 v1(127.61,42.1) ; C338.1 v3(144.15,40) ; C344.1 v1(127.73,41.1) ; R4077.2 v3(66.01,94.25) ; v3(65.15,94.26) R4076.2 ; R709.1 v3(141.46,101.78) ; C488.2 127.9,74.75 127.29,74.75 v3(127.2,74.67) ; v3(144.45,75.8) C372.2 ; v1(139.43,67.32) 138.97,67.78 U401.T9 ; C487.2 v3(144.32,44) ; v3(12.44,14.28) 12.25,14.46 D1000.2 ; C326.1 v3(127.15,76.8) ; U401.G8 v1(137.76,75.38)
  TOP w0.5: MR58.1 86.26,79.9 v3(85.95,79.9) ; C411.2 v3(45.05,25.69) ; v3(73.15,6.75) 72.65,6.25 MPCIE1.B26 ; MPCIE1.B80 126.65,6.25 v3(126.15,6.75) ; v3(118.15,6.75) 118.15,6.7 118.65,6.2 MPCIE1.B72 ; v3(96.14,87.73) 96.05,87.82 MR1240.1 ; C4008.2 v3(164.21,30.36) ; v3(122.15,6.75) 122.65,6.25 MPCIE1.B76 ; R610.1 70.35,101.8 70.84,101.31 R609.1 v3(71.25,100.6) ; D1004.2 12.55,23.8 v3(12.45,23.7) ; U2.4 v3(81.35,88.69) ; D2500.2 v3(20.45,88.4) ; R4108.2 144.59,28.14 v3(145.34,28.14) ; R1001.2 R1029.2 v3(24.47,22.3) ; C801.1 v3(86.66,72.61) ; v3(124.15,6.75) 123.65,6.25 MPCIE1.B77 ; v3(73.55,106.3) 73.61,106.36 Q852.2 ; v3(150.05,17.2) 150.05,17.68 Q4103.3 151.45,17.68 v3(151.45,17.2) ; v3(99.45,87.9) 100.25,88.7 R4039.2 ; MPCIE1.B65 111.65,6.25 v3(112.15,6.75) ; MR50.1 v3(93.85,88) ; R2526.2 20.16,84.31 v3(20.25,84.4) R2524.2 ; MR44.1 v3(87.76,87.89) ; Q1803.2 v3(30.25,82.54) ; v3(62.15,6.75) 62.65,6.25 MPCIE1.B16 ; v3(142.15,35.7) 143.08,35.7 MC379.2 142.6,34.8 v3(142.05,34.8) ; v3(52.65,13.6) 52.65,13.7 53.14,14.19 C33.2 ; v3(116.15,6.75) 115.65,6.25 MPCIE1.B69 ; v3(78.15,6.7) 78.15,6.65 78.65,6.15 MPCIE1.B32 ; C44.2 107.25,107.62 v3(107.25,106.9) ; v3(91.15,6.75) 90.65,6.25 MPCIE1.B44 ; Q4050.2 93.34,97.29 v3(93.5,97.13) ; C843.2 v3(19.05,44.4) ; MR49.1 94.82,88.58 v3(94.82,87.62) ; MPCIE1.B53 99.65,6.37 v3(100.01,6.73) ; Q4007.2 v3(116.2,99.45) ; v3(104.15,6.75) 103.65,6.25 MPCIE1.B57 ; v3(71.15,6.75) 71.25,6.75 71.65,6.35 MPCIE1.B25 ; MPCIE1.B61 107.65,6.1 108.15,6.6 v3(108.15,6.75) ; R4111.2 v3(156.75,31.9) ; v3(68.85,106.4) 69.02,106.57 Q4010.2 ; C1002.2 v3(21.45,21.3) ; Q4006.2 v3(111.63,99.48) ; Q4011.2 v3(147.29,23.56) ; v3(17.35,71.4) 17.15,71.6 R2530.2 ; v3(62.95,99.4) 62.77,99.22 C603.2 ; v3(70.65,90.8) 70.55,90.9 R4072.2 ; v3(155.95,24.8) 155.36,24.8 C4102.2 155.36,25.8 v3(155.95,25.8) ; MR1241.1 v3(80.92,85.3) ; D4404.2 v3(16.05,58.4) ; v3(110.05,6.7) 110.09,6.7 110.11,6.67 110.23,6.67 110.65,6.25 MPCIE1.B64 ; v3(75.15,6.75) 75.2,6.75 75.65,6.3 MPCIE1.B29 ; v3(15.95,93.5) 15.95,92.51 C2540.2 16.45,92.2 16.85,92.6 v3(16.85,93.5) ; 16.05,86.72 v3(16.05,87.4) ; v3(114.15,6.75) 114.65,6.25 MPCIE1.B68 ; v3(24.47,18.8) R1028.2 R1002.2 ; C4015.2 106.21,95.57 v3(106.76,95.02) ; MPCIE1.A4 48.75,3.6 48.75,6.08 v2(49.49,6.83) ; D2501.2 v3(20.45,87.1) ; Q1804.2 v3(25.41,83.66) ; R2027.2 v3(5.55,66) ; v3(89.15,6.75) 89.15,6.7 89.65,6.2 MPCIE1.B43 ; MPCIE1.B56 102.65,5.6 102.45,5.8 102.45,6.45 v3(102.15,6.75) ; v3(142.41,81.17) 143.3,81.17 C368.2 143.1,80.14 v3(142.48,80.14) ; MPCIE1.A49 v3(95.65,6.7) ; v3(81.15,6.7) 81.65,6.2 MPCIE1.B35 ; C2006.2 v3(10.45,72.5) ; MPCIE1.B52 98.65,5.6 98.45,5.8 98.45,6.45 v3(98.15,6.75) ; v3(54.28,15.34) 54.28,14.88 C27.2 55.55,13.61 v3(55.85,13.61) ; v3(93.16,6.75) 93.19,6.75 93.65,6.3 MPCIE1.B47 ; R4063.2 v3(143.55,22.3) ; v3(98.81,98.86) 98.42,98.86 Q4013.2 ; R4047.2 v3(103.83,97.48) ; C703.2 146.35,106.9 v3(145.45,107.8) ; MPCIE1.B22 68.65,6.25 v3(69.15,6.75) ; R2003.2 v3(5.35,66.9) ; MR48.1 v3(97.05,88.1) ; MR55.1 v3(98.25,88.1) ; C1003.2 v3(21.47,24.8) ; J1601.15 J1601.22 ; v3(10.45,67.7) C2003.2 R2001.2 R2029.2 10.36,65.1 v3(10.35,65.1) ; v3(159.64,16.29) R4110.2 v3(158.28,17.37) ; Q2701.2 v3(22.49,44.39) ; MR43.1 v3(65.46,59.48) ; v3(7.75,65.2) 8.35,65.2 8.66,65.51 R2028.2 C2002.2 R2002.2 v3(7.95,67.8) ; Q4102.3 148.4,28.29 v3(149.55,28.29) ; Q842.2 v3(134.11,108.16) ; R4113.2 v3(162.55,31.1) ; MPCIE1.B39 85.65,6.25 v3(85.15,6.75) ; MR56.1 v3(65.41,60.35) ; MR45.1 88.35,78.57 88.24,78.46 v3(88.27,78.46) ; R4073.2 v3(70.75,92) ; v3(51.3,6.8) 51.65,6.45 MPCIE1.B7 ; v3(59.25,7.1) 59.25,7 59.65,6.6 MPCIE1.B13 ; D4403.2 v3(16.05,59.8) ; C4400.2 v3(94.45,104.78) ; R715.2 v3(155.74,104.09) ; v3(72.85,104.2) 72.56,104.2 R4053.2 ; v3(18.1,83.35) 18.43,83.03 D2502.2 ; Q4401.2 v3(97.91,105.26) ; MPCIE1.B73 119.65,6.1 120.15,6.6 v3(120.15,6.75) ; Q4016.2 v3(103.3,98.35) ; MPCIE1.B21 67.65,6.25 v3(67.15,6.75) ; R615.2 v3(60.17,97.62) ; v3(65.15,6.75) 64.65,6.25 MPCIE1.A18 ; C82.2 v3(65.8,30.75) ; C1005.2 v3(14,16.61) ; C47.2 v3(152.86,106.99) ; R1003.2 v3(23.47,15.23) ; R4408.1 v3(88.81,102.03) ; v3(87.15,6.75) 86.65,6.25 MPCIE1.B40 ; R4106.2 v3(150.16,26.09) ; C4100.2 v3(154.35,30.9) ; MR53.1 v3(79.56,88.01) ; R4061.1 v3(94.95,97.3) ; C410.2 51.23,16.77 v3(51.23,17.37) ; D1003.2 v3(12.65,22.5) ; C83.2 v3(71.25,30.8) ; C841.2 v3(144.75,104.7) ; Q1601.2 v3(15.61,49.14) ; D4406.2 v3(15.95,61.4) ; v3(83.15,6.75) 82.65,6.25 MPCIE1.B36 ; C2001.2 v3(5.25,67.8) ; C1006.2 v3(13.9,19.01) ; R2522.2 v3(31.85,84.9) ; C4402.2 v3(144.55,22.3) ; C43.2 v3(117.35,107.9) ; C4003.2 v3(93.05,92) ; C2722.2 18.11,59.8 v3(18.66,60.36) ; C4401.2 v3(72.15,108.7) ; R4409.2 v3(26.14,69.2) ; C1001.2 v3(21.47,17.79) ; R1027.2 v3(24.47,15.3) ; C1004.2 v3(13.78,14.21) ; C57.2 v3(90.11,102.11) ; R39.2 v3(104.95,89.1) ; Q4009.2 v3(107.05,99.38) ; R4043.2 v3(112.48,108.57) ; C2005.2 v3(7.95,72.5) ; Q4100.2 v3(156.3,27.35) ; C2004.2 v3(5.55,72.5) ; R4403.2 v3(91.65,107.9) ; Q841.2 v3(132.09,108.16)
  TOP w0.503: 42.02,93.24 C631.2 ; C631.2 42.95,93.55 ; C631.2 42.02,95.74 ; C631.2 41.08,95.42 ; C631.2 41.08,93.55 ; C631.2 41.5,93.27 ; C631.2 43.27,94.49 ; C631.2 42.95,95.42
  TOP w0.8: v2(154.18,97.99) 154.18,97.44 C706.2 ; C606.2 v2(62.92,107.6) ; v2(154.1,101.73) U701.3 ; v2(55.65,106.04) 55.65,106.68 C608.1 ; C708.2 v2(164.05,86) ; U601.3 v2(62.79,101.7)
  L2_INNER w0.1: MJ1001.6 0.61,78.98 0.61,82.22 MJ1001.8 0.58,83.57 0.58,86.76 MJ1001.10
  L2_INNER w0.6: 4.62,10.57 4.62,9.88 3.66,8.92 J1601.25 3.66,7.62 ; 4.75,5.5 4.75,6.53 3.66,7.62 ; 3.24,5.5 3.66,5.92 3.66,7.62 ; MJ1001.10 MJ1001.5 1.28,89.99 ; MJ1001.6 1.28,77.26 ; MJ1001.7 3.5,80.6
  L3_INNER w0.503: J1601.26 6.66,37.5 ; J1601.26 6.66,39.26 ; J1601.26 3.66,37.5 ; J1601.26 2.16,37.5 ; J1601.26 3.66,41.01 ; J1601.26 6.66,41.01 ; J1601.26 5.16,41.01 ; J1601.26 6.66,40.13 ; J1601.30 12.29,36.19 ; J1601.30 9.69,38.59 ; J1601.30 9.69,36.19 ; J1601.30 9.69,37.39 ; J1601.30 10.99,38.59 ; J1601.30 10.99,36.19 ; J1601.30 12.29,38.59 ; J1601.30 12.29,37.39 ; 66.5,35.42 67.04,35.66 ; 67.04,35.66 67.04,35.14 ; 67.04,35.66 67.46,35.24 ; 67.04,35.66 66.51,35.66 ; 67.04,35.66 66.5,35.91 ; 67.04,35.66 66.62,36.08 ; 67.04,35.66 66.62,35.24 ; 67.04,35.66 66.8,35.12 ; 3.67,16.27 J1601.C6 ; J1601.C6 4.66,16.45 ; J1601.C6 4.3,16.46 ; J1601.C6 5.12,15.63 ; J1601.C6 3.67,15 ; J1601.C6 4.3,14.81 ; J1601.C6 3.95,14.82 ; J1601.C6 3.48,15.63 ; 9.4,47.01 MJ2501.20 ; MJ2501.20 11.45,48.16 ; MJ2501.20 7.35,49.32 ; MJ2501.20 7.35,47.01 ; MJ2501.20 9.4,49.32 ; MJ2501.20 11.45,49.32 ; MJ2501.20 11.45,47.01 ; MJ2501.20 7.35,48.16 ; HS2.25 68.76,40.29 ; HS2.25 67.97,39.5 ; HS2.25 68.51,40.27 ; HS2.25 67.99,39.74 ; HS2.25 69.06,39.98 ; HS2.25 68.09,40.16 ; HS2.25 68.94,40.16 ; HS2.25 69.04,39.74 ; 8.56,15.63 J1601.C5 ; J1601.C5 10.01,16.27 ; J1601.C5 10.01,15 ; J1601.C5 9.74,16.45 ; J1601.C5 10.2,15.63 ; J1601.C5 9.38,16.46 ; J1601.C5 9.03,14.82 ; J1601.C5 9.38,14.81 ; 66.4,39.03 HS2.32 ; HS2.32 67.17,39.57 ; HS2.32 66.5,38.61 ; HS2.32 66.92,39.56 ; HS2.32 66.5,39.45 ; HS2.32 66.38,38.79 ; HS2.32 66.68,38.48 ; HS2.32 67.34,39.45 ; J1601.25 5.16,10.28 ; J1601.25 6.66,8.53 ; J1601.25 6.66,9.4 ; J1601.25 6.66,10.28 ; J1601.25 3.66,6.77 ; J1601.25 6.66,6.77 ; J1601.25 2.16,6.77 ; J1601.25 3.66,10.28 ; 9.69,11.59 J1601.29 ; J1601.29 12.29,10.39 ; J1601.29 9.69,9.19 ; J1601.29 9.69,10.39 ; J1601.29 10.99,11.59 ; J1601.29 10.99,9.19 ; J1601.29 12.29,9.19 ; J1601.29 12.29,11.59 ; 70.98,36.79 HS2.27 ; HS2.27 71.53,37.56 ; HS2.27 71.51,37.32 ; HS2.27 71.23,37.87 ; HS2.27 71.41,36.9 ; HS2.27 70.74,36.77 ; HS2.27 70.98,37.85 ; HS2.27 71.41,37.74 ; 9.69,28.91 10.99,27.7 ; 10.99,27.7 12.29,27.7 ; 10.99,27.7 10.99,26.5 ; 10.99,27.7 10.34,26.5 ; 10.99,27.7 12.29,26.5 ; 10.99,27.7 9.69,26.5 ; 10.99,27.7 12.29,28.91 ; 10.99,27.7 10.99,28.91 ; 9.69,20.7 10.99,20.7 ; 10.99,20.7 9.69,19.5 ; 10.99,20.7 10.99,21.91 ; 10.99,20.7 10.99,19.5 ; 10.99,20.7 12.29,19.5 ; 10.99,20.7 12.29,20.7 ; 10.99,20.7 12.29,21.91 ; 10.99,20.7 10.34,19.5 ; HS2.28 70.56,35.32 ; HS2.28 70.14,35.22 ; HS2.28 70.66,35.75 ; HS2.28 69.89,35.2 ; HS2.28 70.68,35.99 ; HS2.28 70.56,36.17 ; HS2.28 69.59,35.5 ; HS2.28 69.72,35.32 ; MJ2501.23 5.19,49.32 ; MJ2501.23 1.69,48.16 ; MJ2501.23 1.69,47.01 ; MJ2501.23 3.44,49.32 ; MJ2501.23 5.19,47.01 ; MJ2501.23 3.44,47.01 ; MJ2501.23 5.19,48.16 ; MJ2501.23 1.69,49.32 ; 1.7,61.51 MJ2501.22 ; MJ2501.22 3.45,63.82 ; MJ2501.22 5.2,63.82 ; MJ2501.22 1.7,62.66 ; MJ2501.22 5.2,62.66 ; MJ2501.22 1.7,63.82 ; MJ2501.22 3.45,61.51 ; MJ2501.22 5.2,61.51 ; HS2.26 70.83,39.32 ; HS2.26 70.93,38.89 ; HS2.26 69.99,39.32 ; HS2.26 70.83,38.47 ; HS2.26 70.65,39.44 ; HS2.26 70.95,39.14 ; HS2.26 69.86,39.14 ; HS2.26 70.41,39.42 ; 68.61,34.54 HS2.29 ; HS2.29 68.19,34.65 ; HS2.29 69.04,34.65 ; HS2.29 68.37,34.52 ; HS2.29 69.14,35.07 ; HS2.29 69.16,35.31 ; HS2.29 68.09,35.07 ; HS2.29 68.07,34.83 ; 7.35,63.82 MJ2501.21 ; MJ2501.21 11.45,61.51 ; MJ2501.21 7.35,62.66 ; MJ2501.21 11.45,63.82 ; MJ2501.21 7.35,61.51 ; MJ2501.21 9.4,61.51 ; MJ2501.21 9.4,63.82 ; MJ2501.21 11.45,62.66 ; 65.68,37.15 HS2.31 ; HS2.31 66.23,37.91 ; HS2.31 65.81,36.97 ; HS2.31 66.23,36.86 ; HS2.31 65.7,37.39 ; HS2.31 65.68,37.63 ; HS2.31 65.99,36.84 ; HS2.31 65.81,37.81
  BOTTOM w0.1: v1(125.22,62.31) 125.22,62.31 125.22,62.31 125.22,62.31 125.19,62.31 125,62.12 121.11,62.12 120.84,62.4 v3(120.84,62.46) ; v3(123.79,51.47) 123.58,51.26 123.58,51.12 123.03,50.57 122.87,50.57 122.37,50.06 C374.2 ; C382.2 MC382.2
  BOTTOM w0.2: v1(136.88,76.17) 136.87,76.17 136.96,76.18 137.69,76.18 138.08,76.58 U401.E8 ; 133.37,76.58 133.5,76.58 133.89,76.97 134.57,76.97 v1(134.87,77.27) ; v3(131.11,36.98) 131.21,36.98 131.55,37.32 132.2,37.32 132.31,37.43 132.38,37.43 132.56,37.62 ; v1(101.65,51.4) 102.76,51.4 103.19,51.82 113.58,51.82 113.59,51.83 113.75,51.83 113.75,51.83 123.49,51.83 123.79,51.52 v3(123.79,51.47) ; C132.2 104.12,67.13 104.12,66.52 104.97,65.67 v1(113.12,65.67) 113.12,65.47 114.58,64 116.33,64 v1(116.35,64.03) 116.38,64 121.92,64 v3(122.26,63.66) ; v1(134.66,40.41) 134.57,40.41 133.84,40.41 133.45,40.02 133.37,40.02 ; C121.2 99.39,49.17 99.39,49.81 99.75,50.16 v1(99.75,50.2) 99.88,50.34 103.49,50.34 104.06,50.91 114.13,50.91 114.14,50.92 120.69,50.92 120.72,50.9 120.75,50.9 120.91,50.74 121.75,50.74 v1(121.8,50.7) ; v1(101.69,65.93) 103.33,65.93 104.63,64.63 112.31,64.63 113.99,62.95 120.32,62.95 120.81,62.46 v3(120.84,62.46) ; v1(139.39,80.52) 139.36,80.49 139.36,80.24 139.31,80.19 139.31,79.98 139.36,79.94 139.36,79.61 139.33,79.58 139.33,79.34 U401.B9 ; v1(139.76,39.74) 139.69,39.81 139.69,40.25 139.13,40.81 U201.F9 ; v1(135.76,73.73) 135.71,73.69 135.27,73.69 135.18,73.78 133.85,73.78 133.45,73.38 133.37,73.38
  BOTTOM w0.3: 132.56,70.97 131.97,70.97 v1(131.85,71.1) ; v1(92.06,61.89) 92.49,61.47 C87.2 ; v1(92.06,61.89) 91.6,62.35 C195.2 ; v1(92.06,61.89) 92.44,62.26 C85.2 ; v3(96.95,68.05) 96.35,68.65 C61.2 ; R2500.2 82.23,65.36 v1(81.4,66.2) ; C188.2 93.66,62.36 v1(94.12,61.89) 94.62,62.38 C137.2 ; U401.J8 138.15,73.38 v1(137.76,73.77) ; v1(91.13,62.92) 90.66,63.4 C190.2 90.61,63.47 89.76,63.47 C143.2 ; U202.T1 139.42,49.27 v1(139.43,49.27) ; v1(139.55,71.13) 139.4,70.97 U401.M9 ; v1(139.43,67.32) 139.42,67.32 U401.T9 ; v1(90.15,52.75) 90.62,53.22 C152.2 ; v1(139.53,41.59) 139.5,41.59 139.47,41.62 138.16,41.62 ; v1(131.34,38.78) 131.4,38.83 131.93,38.83 132.27,39.17 132.52,39.17 132.56,39.22 ; v1(89.25,57.1) 89.25,57.14 v1(88.25,58.14) 87.77,57.66 C164.2 ; 138.97,47.22 v1(139.56,47.22) ; v1(131,75.37) 131.03,75.37 131.07,75.42 131.1,75.42 131.42,75.73 131.98,75.73 132.03,75.78 132.56,75.78 ; v1(94.93,66.11) 94.32,65.51 C135.2 ; C303.1 101.66,74.19 101.44,73.97 v1(100.98,73.97) ; 138.97,45.62 v1(139.59,45.62) ; v1(88.93,64.92) 89.03,64.92 89.49,65.38 89.64,65.38 ; v1(132.97,43.62) 133.37,43.22 133.37,43.22 ; v1(131.76,74.97) 133.37,74.97 ; v3(141.85,51) 142.53,51 MC131.2 142.29,52 v3(141.75,52) ; 134.16,37.62 v1(133.76,38.02) ; R9.2 86.84,56.6 85.87,56.6 C165.2 ; 137.78,39.61 137.78,39.8 138,40.02 U202.E2 ; U401.E8 U402.E1 U402.D1 ; R12.1 82.97,55.92 C1508.1 ; 132.56,47.22 132.03,47.22 v1(131.97,47.27) ; 132.56,69.38 132.56,69.38 132.09,69.38 132.04,69.34 132,69.34 v1(132,69.33) ; C344.1 v1(127.73,41.1) ; 133.37,77.38 133.37,77.43 133.01,77.78 v1(132.96,77.78) ; C59.2 80.58,62.41 81.67,62.41 82.04,62.04 82.77,62.04 82.79,62.02 83.15,62.02 83.21,61.97 ; v1(84.47,57.81) 84.47,57.71 83.98,57.23 83.49,57.23 83.42,57.29 R1500.2 ; v3(89.25,60.9) 89.25,60.8 v1(90.15,59.9) v1(91.05,59) 91.95,58.1 v1(92.05,58.1) 91.1,57.15 v1(91.03,57.15) 91.03,57.23 v1(90.15,58.1) v1(89.25,59) ; C70.2 94.4,67.51 v1(93.91,68) ; C153.2 90.2,55.02 v1(91.05,55.02) 91.71,54.37 92.04,54.37 92.06,54.35 C151.2 ; v1(131.84,45.56) 131.89,45.62 132.56,45.62 ; C310.1 v1(127.61,42.1) ; C357.2 144.28,45.76 v3(144.31,45.72) ; C448.2 R208.2 128.43,68.98 v3(128.25,68.8) ; 132.56,79.78 132.56,79.78 v1(132.12,79.34) 132.5,78.97 132.56,78.97 ; C312.1 v1(127.78,40.1) ; 75.13,38.83 75.13,37.12 72.64,34.63 72.64,21.39 66.06,14.81 63.02,14.81 60.81,12.6 v3(59.38,12.6) ; 132.56,67.78 132.52,67.73 132.52,67.67 132.43,67.58 132.43,67.49 132.33,67.39 v1(132.33,67.23) ; v1(132.37,49.34) 132.56,49.13 132.56,48.81 ; v1(131.97,41.65) 131.97,41.65 132,41.62 132.56,41.62 ; 138.97,37.62 U201.A9 139.14,36.81 139.72,37.4 v1(139.72,37.41) ; R220.2 v3(127.45,71.8) ; 137.37,78.97 v1(137.76,78.58) ; v3(130.39,39.69) 131.91,39.69 132.1,39.88 132.43,39.88 132.56,40.02 ; R229.1 141.15,56.5 v3(141.62,56.04) ; C79.2 92.12,67.14 ; v1(91.05,60.9) v1(92.05,59.9)
  BOTTOM w0.4: R7.1 84.01,60.85 v1(83.49,61.37) ; C333.1 114.33,47.05 v1(114.32,47.05) ; C123.2 123.13,62.79 v3(122.26,63.66) ; v3(143.39,66.29) 143.39,67.02 C354.1 ; v3(144.24,40.91) 143.73,40.91 C309.1 ; C129.2 116.61,34.69 117.06,35.13 v1(117.06,35.23) ; C1508.1 82.82,56.05 v1(82.82,56.66) ; v1(87.25,57.19) 86.85,56.78 R9.2 ; v1(97.31,63.81) 97.43,63.94 C124.2 ; C169.2 88.74,55.55 v1(88.27,55.08) 87.71,55.63 C185.2 ; v1(85.42,53.25) 84.04,53.25 R35.2 ; v1(69.75,59.3) 70.32,59.86 70.32,60.5 C68.2 ; R292.2 96.93,46.46 97.44,45.95 v1(97.45,45.95) ; v3(144.22,71.17) 144.04,70.99 C320.1 ; C168.2 88.57,61.48 89.14,60.9 v3(89.25,60.9) 89.41,61.06 C187.2 ; C141.2 108.84,70.57 108.84,70.58 v1(108.87,70.58) ; v3(28.25,28.6) 28.25,28.4 28.5,28.15 U1999.7 ; 100.44,69.15 100.45,69.17 100.45,70.16 v1(100.58,70.3) ; v1(86.57,53.98) 86.57,54.03 86.11,54.5 ; C173.2 88.68,62.46 v1(88.22,62.92) ; v1(144.28,74.25) 143.94,74.25 143.62,73.94 C362.2 ; v3(144.25,70.4) 143.81,69.97 143.48,69.97 C463.2 ; D1006.2 18.32,17.73 v3(17.85,18.2) ; v1(91.13,62.92) 91.57,62.48 C195.2 ; C1007.2 v3(25.35,29.1) C1008.2 ; C316.1 v3(140.2,58.37) ; v1(86.28,60.91) 85.49,60.13 MC174.2 ; v1(121.59,65.31) 121.59,65.3 121.4,65.11 121.4,64.69 C136.2 ; U401.P9 v1(139.56,69.38) ; C385.1 101.31,75.3 100.99,74.98 100.99,74.83 v1(100.86,74.7) ; v1(119.17,49.71) 119.17,50.06 118.86,50.37 C339.1 ; C127.2 106.75,47.23 106.69,47.28 106.69,47.55 v1(107.05,47.9) ; C325.1 116.86,82.54 v1(117.37,82.03) ; v1(137.78,39.61) 137.78,39.61 137.78,39.59 138.16,39.22 138.16,39.22 ; v3(127.75,39.15) 127.79,39.1 C311.1 ; v3(142.48,80.14) 142.98,80.64 MC133.2 ; C1052.2 78.65,54.4 v1(78.45,54.6) ; v3(88.33,59.9) 88.35,59.9 v1(89.25,59) ; v1(104.85,49.6) 104.85,50.13 C370.2 ; C2516.1 81.33,67.87 v1(81.4,67.8) 81.76,67.44 C2517.1 ; v1(65.74,65.75) 65.33,65.34 MR71.1 ; v1(83.49,61.37) 83.49,61.18 82.99,60.68 C67.2 ; v1(83.49,61.37) 83.49,61.69 83.21,61.97 ; C487.2 v3(144.32,44) ; v3(78.29,61) 76.81,61 C53.1 R22.1 ; C194.2 93.62,57.55 v1(94.1,57.06) 94.53,57.49 C172.2 ; C71.2 96.58,67.13 96.95,67.5 v3(96.95,68.05) ; C4020.2 85.8,58.48 86.36,58.48 C183.2 86.99,58.44 86.99,58.44 87.28,58.16 v1(87.28,58.16) 87.74,57.7 C164.2 ; v3(144.2,71.94) 143.44,71.94 R216.2 ; C308.1 113.45,66 v1(113.12,65.67) ; v1(78.6,57.56) 78.69,57.56 78.7,57.55 79.31,57.55 C1506.2 79.91,57.41 79.91,57.4 C1507.1 ; v3(59.25,7.1) 59.25,7 58.8,6.55 58.8,3.65 MPCIE1.A12 ; R202.2 144.17,46.7 v3(144.34,46.52) ; v1(78.53,53.03) 78.53,52.9 78.73,52.7 79.28,52.7 C1054.2 79.59,52.36 C1055.2 ; v1(76.07,57.43) 76.24,57.26 C1500.2 77.3,56.98 77.49,56.98 77.49,56.98 v3(77.87,56.98) ; v3(141.06,58.9) 141.12,58.96 141.12,60.03 R230.1 ; v3(144.21,42.42) 143.89,42.1 C340.1 ; C132.2 103.09,67.49 102.77,67.81 v3(102.71,67.81) ; U1999.1 v3(32.4,28.5) ; v1(115.13,75.73) 115.13,75.65 115.6,75.18 C314.1 ; C350.1 143.87,67.58 143.87,67.52 v3(144.15,67.23) ; C800.1 85.78,68.39 85.78,68.1 v1(85.75,68.07) ; v1(73.95,70.1) 73.28,69.44 MR70.1 ; C150.2 94.38,54.07 v1(94.9,54.07) 95.26,54.43 C120.2 ; v3(128.15,6.8) 128.15,6.67 128.55,6.28 128.55,3.6 MPCIE1.A82 ; v1(99.2,59.38) 99.22,59.38 99.78,58.83 C140.2 ; R210.2 C486.2 129.86,44.19 v3(129.95,44.1) ; v1(94.12,61.89) 93.69,61.45 C86.2 ; v1(125.65,65.75) 125.65,65.75 125.66,65.76 126.14,65.76 126.31,65.93 C306.1 ; v3(143.51,58.75) 143.25,58.48 C381.2 142.47,57.48 v3(142.32,57.33) ; v1(144.35,47.36) 144.12,47.36 143.88,47.6 C322.1 ; R294.2 99.28,48.52 C121.2 ; R76.1 70.07,65.61 v1(70,65.61) ; MC367.2 v3(142.16,62.52) ; C321.1 127.85,74.2 127.39,74.67 v3(127.2,74.67) ; C2510.1 80.56,65.72 C2511.1 80.9,65.7 v1(81.4,66.2) ; v3(81.35,61.38) 81.36,61.38 81.36,60.55 C1504.1 80.61,60.39 C1503.2 ; v3(101.47,47.77) 101.46,47.76 C335.1 ; v3(142.7,55.38) 142.97,55.11 MC130.2 ; v3(124.59,48.74) MC380.2 v1(124.56,49.69) ; C326.1 v3(127.15,76.8) ; v3(143.83,56.52) 143.98,56.38 C130.2 ; C386.1 v3(126.59,78.14) ; v1(81.37,56.62) 81.37,57.18 C1505.1 ; C361.2 107.02,49.24 v1(107.02,49.62) ; v1(96.91,70.46) 97.66,69.7 C62.2 ; v1(125.19,65.2) 125.18,65.2 125.18,65.11 124.8,64.74 C341.1 ; v3(144.55,75.02) 143.86,75.02 C337.1 ; v1(94.8,49.9) 94.8,49.73 95.46,49.07 C295.2 96.14,47.84 v1(96.27,47.84) ; C384.1 100.88,43.47 v3(100.59,43.77) ; v3(127.18,73.18) 127.24,73.25 128,73.25 C302.1 ; v1(92.57,65.82) 92.57,65.9 C80.2 92.12,66.5 92.12,67.14 ; v3(144.28,43.22) 144.16,43.1 R212.2 ; v1(121.8,50.7) 121.8,50.44 C374.2 ; U1999.4 30.45,28.3 v3(30.15,28.6) ; v3(74.52,66.4) 74.83,66.7 C2512.2 ; C58.2 97.7,72.99 v3(98.85,72.99) ; v1(64.65,68.15) 64.71,68.21 C90.2 ; C1501.1 78.23,59.84 v1(78.71,59.36) 79.19,59.84 C1502.1 ; U12.2 69.55,69.09 69.04,68.58 ; v1(95.35,62.6) 95.35,62.35 C134.2 ; C93.2 65.9,71.72 65.9,71.64 v1(65.8,71.54) ; C307.1 v3(144.25,38.9) ; v3(144.45,77.35) 143.99,77.35 C305.1 ; C139.2 101.32,69.3 v1(101.88,69.87) ; v1(92.12,68.07) 91.85,67.79 C79.2 ; C372.2 v3(144.45,75.8) ; C193.2 93.47,55.6 v1(93.02,56.05) 93,56.08 MC176.2 ; C297.2 97.54,50.12 R301.2 98.15,50.2 v1(98.15,50.2) ; 138.16,43.22 v1(138.56,43.61) ; C338.1 v3(144.15,40) ; v3(144.45,76.58) 143.87,76.58 C342.1 ; v3(144.18,69.12) 143.57,69.12 C348.1 ; v3(127.23,46.97) 127.31,46.88 127.37,46.88 127.39,46.86 127.66,46.86 127.85,46.66 C336.1 ; D1005.2 v3(17.77,16.02) ; C349.1 110.76,71.94 v1(110.76,71.44) ; 101.06,67.3 101.45,67.3 v1(101.85,67.7) 101.85,67.73 101.29,68.29 C128.2 ; U401.G9 v3(139.56,74.97) ; TP503.1 84.15,75.54 84.41,75.28 C170.2 ; C2515.2 v3(76.65,66.75)
  BOTTOM w0.5: R853.2 v3(22.52,84.17) ; R864.2 57.44,35.22 v3(57.1,34.87) ; U851.8 51.14,42.7 R854.2 51.24,42.71 v3(51.85,42.1) ; MR54.1 89.86,70.99 v1(89.94,71.07) ; v3(81.74,77.02) C4001.2 81.06,77.85 v1(81.17,77.85) ; MPCIE1.A24 70.65,6.25 v3(71.15,6.75) ; C78.2 C77.2 90.83,79.9 90.93,80.01 v3(90.93,80.12) ; C78.2 93.14,78.69 C144.2 94.43,79.4 v3(94.77,79.73) ; C78.2 92.73,80.12 v3(92.46,80.39) ; Q1201.2 v3(73.55,106.3) ; v3(108.15,6.75) 108.2,6.75 108.65,6.3 MPCIE1.A62 ; C92.2 72.47,72.54 v3(72.01,72.54) ; v3(87.15,6.75) 87.65,6.25 MPCIE1.A41 ; v1(79.35,6.7) 79.95,6.7 80.65,6 MPCIE1.A34 ; MPCIE1.A37 83.65,6.2 83.15,6.7 v3(83.15,6.75) ; v3(114.15,6.75) 114.05,6.75 113.65,6.35 MPCIE1.A67 ; v3(81.71,80.42) 81.71,79.48 81.39,79.15 C196.2 80.67,79.68 v3(80.67,80.42) ; MPCIE1.A28 74.65,6.25 v3(75.15,6.75) ; v3(10.95,30) 10.55,29.61 J1601.3 J1601.11 J1601.19 v3(2.35,29.61) ; v1(70.99,63.65) C66.2 ; v3(98.15,6.75) 98.05,6.75 97.65,6.35 MPCIE1.A51 ; SW4001.3 95.08,97.42 v3(94.95,97.3) ; MPCIE1.A18 64.65,6.25 v3(65.15,6.75) ; v3(94.18,74.65) 93.65,75.18 R297.2 R296.2 ; v3(118.15,6.75) 117.65,6.25 MPCIE1.A71 ; v1(92.57,65.82) 91.55,64.8 R60.2 ; C175.2 74.33,81.98 75.08,81.23 v3(75.59,81.23) ; C175.2 v3(75.61,81.99) ; C175.2 74.24,81.89 C186.2 ; C189.2 93.7,58.49 v1(94.12,58.06) 94.6,58.53 C184.2 ; v3(110.05,6.7) 110.05,6.65 109.65,6.25 MPCIE1.A63 ; C155.2 76,54.84 C154.2 ; MR46.1 95.82,86.22 v3(96.19,85.85) ; v3(30.35,16.5) 30.74,16.11 R1617.2 ; v1(78.08,44.42) 77.76,44.11 C73.2 ; v3(93.16,6.75) 93.1,6.75 92.65,6.3 MPCIE1.A46 ; R32.1 87.27,71.99 v3(86.66,72.61) ; MPCIE1.A27 73.65,6.25 v3(73.15,6.75) ; v3(142.15,35.7) 142.98,35.7 MC378.2 142.7,34.8 v3(142.05,34.8) ; v3(98.42,96.98) 97.98,97.42 SW4001.4 ; MPCIE1.A45 91.65,6.25 v3(91.15,6.75) ; MPCIE1.A70 116.65,6.25 v3(116.15,6.75) ; R3600.1 v3(102.25,84.3) ; C2513.1 81.32,63.99 81.33,64 v1(81.33,64.61) ; J4004.4 103.02,93.83 v3(103.63,93.22) ; C75.2 77.03,45.38 76.6,45.38 v3(76.53,45.3) 76.53,46.27 C74.2 ; C868.2 v3(48.55,28.6) ; C846.2 v3(18.1,83.35) ; v3(69.1,18.65) C866.2 67.93,17.78 v3(67.65,17.5) ; MPCIE1.A42 88.65,6.25 v3(89.15,6.75) ; MPCIE1.A66 112.65,6.25 v3(112.15,6.75) ; v3(74.5,40.2) 75.13,39.57 C89.2 75.13,38.83 74.4,38.1 v3(74.05,38.1) ; C148.2 v3(75.41,59.7) ; v3(120.15,6.75) 120.65,6.25 MPCIE1.A74 ; v3(45.62,15.6) 45.75,15.6 46.44,16.29 C21.2 ; MPCIE1.A20 66.65,6.25 v3(67.15,6.75) ; v3(54.46,45.52) 54.46,46.19 C852.2 55.08,46.7 55.52,46.25 v3(55.52,45.54) ; v3(69.85,106.4) 69.55,106.1 Q1200.2 ; MR51.1 v3(28.48,24.86) ; U861.8 v3(55.24,32.56) ; v3(78.15,6.7) 77.65,6.2 MPCIE1.A31 ; C4002.2 81.83,74.6 v1(82.55,74.6) ; C167.2 88.62,74.09 v1(88.75,73.96) ; v3(124.15,6.75) 124.65,6.25 MPCIE1.A78 ; v1(106.05,6.7) 105.65,6.3 MPCIE1.A59 ; Q851.2 v3(23.28,73.57) ; MPCIE1.A38 84.65,6.25 v3(85.15,6.75) ; v3(83.35,71.09) 83.36,71.1 C156.2 ; v1(75.47,64.61) 76.36,63.73 C88.2 77.14,63.73 77.67,64.31 C63.2 78.65,64.31 R23.2 79.43,62.77 C64.2 C59.2 ; C138.2 v3(116.95,87.7) ; MR47.1 v3(93.29,86.19) ; C145.2 64.65,56.8 v3(64.55,56.9) ; R851.2 22.23,77.5 22.03,77.7 v3(21.35,77.7) ; v3(114.05,87.4) 114.05,88.42 C382.2 113.16,88.92 112.55,88.3 v3(112.55,87.4) ; v3(58.85,10.5) 58.55,10.8 C8.2 C34.1 ; v3(100.01,6.73) 100.65,6.09 MPCIE1.A54 ; v3(122.15,6.75) 122.05,6.75 121.65,6.35 MPCIE1.A75 ; C1624.2 22.44,34.09 v3(22.85,34.5) ; MPCIE1.A4 48.75,3.6 48.75,6.08 v2(49.49,6.83) ; R37.2 v3(101.45,84.9) 101.25,84.7 R298.2 ; MPCIE1.A55 101.65,6.3 101.98,6.63 102,6.63 102.11,6.75 v3(102.15,6.75) ; v3(104.15,6.75) 104.2,6.75 104.65,6.3 MPCIE1.A58 ; v3(69.15,6.75) 69.65,6.25 MPCIE1.A23 ; MPCIE1.A15 61.65,6.25 v3(62.15,6.75) ; SW4002.3 90.64,97.49 v3(90.35,97.2) ; C1051.2 81.22,54.33 v1(82.15,53.41) ; v3(95.65,6.7) MPCIE1.A49 ; C304.1 140.97,84.92 v3(141.55,84.33) ; C1999.1 v3(26.16,34.4) ; C171.2 v3(74.72,71.91) ; MPCIE1.A79 125.65,6.25 v3(126.15,6.75) ; MR52.1 v3(28.21,23.84) ; C2514.1 71.82,64.16 v3(71.64,64.34) 71.64,64.49 72.23,65.08 C2509.2 ; C3600.2 103.25,83.9 103.6,84.25 104.7,84.25 v3(104.76,84.2) 105.25,83.7 C3608.2 ; v3(36.45,45.54) 37.21,46.3 C856.2 37.54,46.65 v3(38.25,47.37) ; J1601.22 v3(2.74,23.89) ; C161.2 v1(80.58,48.6) ; C35.2 v3(59.38,12.6)
  vias: v1(60.85,68) v1(62.55,67.1) v1(67.2,67.09) v1(69.03,67) v1(76.12,54.17) v2(28.05,91.9) v2(28.75,93.2) v2(35.43,20.19) v2(35.43,18.67) v2(35.43,17.14) v2(35.43,15.62) v2(35.43,14.1) v2(36.96,20.19) v2(36.96,18.67) v2(36.96,17.14) v2(36.96,15.62) v2(36.96,14.1) v2(38.48,14.1) v2(40,14.1) v2(41.53,14.1) v2(41.64,91.4) v2(42.35,92.6) v2(43.05,91.4) v2(43.05,14.1) v2(44.58,14.1) v2(47.15,36.9) v2(47.15,35.7) v2(47.25,38) v2(47.45,34.6) v2(54.71,99.77) v2(56.05,99.8) v2(56.45,103.4) v2(56.45,102.2) v2(56.45,101) v2(129.75,89) v2(129.85,93.2) v2(129.85,91.7) v2(129.85,90.3) v2(146.84,78.16) v2(146.85,76.8) v2(146.85,75.5) v2(146.85,74.2) v2(146.85,72.9) v2(146.85,71.5) v2(146.85,70.2) v2(146.85,68.9) v2(146.85,67.6) v2(146.85,66.3) v2(148.15,76.1) v2(148.25,72.8) v2(148.25,70.5) v2(148.25,69.1) v2(148.25,67.6) v2(148.25,66.2) v2(163.05,91.2) v2(163.05,89.8) v2(163.05,88.4) v2(164.45,89.8) v2(164.55,91.2) v2(164.55,88.5) v3(3.99,13.43) v3(5.55,96.2) v3(6.35,96.2) v3(7.75,96.2) v3(8.55,96.2) v3(11.3,13.32) v3(28.65,95.81) v3(28.93,98.27) v3(28.96,97.31) v3(29.75,21) v3(31.34,98.35) v3(31.34,97.28) v3(31.34,95.61) v3(31.37,93.01) v3(31.37,91.92) v3(31.37,90.4) v3(31.37,89.38) v3(33.65,108.7) v3(34.65,108.7) v3(35.65,108.7) v3(36.55,108.7) v3(37.45,108.7) v3(44.65,19.4) v3(44.65,18.2) v3(44.65,17.2) v3(46.48,50.14) v3(46.45,41.6) v3(47.25,42.1) v3(47.4,50.14) v3(48.29,50.14) v3(49.68,30.91) v3(49.65,29.9) v3(49.65,28.9) v3(50.04,18.36) v3(50.09,17.35) v3(54.95,30.8) v3(54.95,29.8) v3(54.95,28.8) v3(55.85,30.8) v3(55.85,29.8) v3(55.85,28.8) v3(59.25,96.4) v3(59.25,95.2) v3(59.95,94.1) v3(59.95,93.3) v3(59.94,92.18) v3(59.95,91.2) v3(59.97,90.3) v3(59.95,89.4) v3(65.86,90.25) v3(66.9,76.76) v3(66.9,75.64) v3(70.69,44.04) v3(71.65,44.98) v3(71.65,44) v3(72.23,53.95) v3(72.55,45) v3(72.55,44) v3(73.25,77.19) v3(73.33,76.07) v3(73.55,52.8) v3(74.35,52.8) v3(74.88,91.39) v3(74.98,92.33) v3(75.55,53.6) v3(76.3,92.41) v3(76.33,91.39) v3(87.05,8.21) v3(87.38,10.87) v3(91.25,8.3) v3(92.8,12.02) v3(140.35,97.5) v3(140.35,96.5) v3(142.85,97.4) v3(142.85,96.5) v3(145.05,97.6) v3(145.05,96.7)
VDD33_27M: length 2.2
  BOTTOM w0.3: U12.8 67.08,68.59 66.69,68.21 C90.1 B72.2
VDD33_100M: length 4.1
  BOTTOM w0.1: U12.4 70.16,68.09 69.97,67.89 69.97,67.1 69.95,67.08
  BOTTOM w0.15: B71.2 C91.1 69.03,66.4 69.5,66.87 69.74,66.87 69.95,67.08
VDDC_BOOT: length 3.9
  TOP w0.8: C605.1 D601.1 60.84,105.18 U601.1
VDDC_EN: length 14.9
  TOP w0.5: C611.1 76.04,103.86 Q852.3 74.55,104.5 73.55,103.5 72.05,103.5 70.29,105.26 Q4010.3 68.96,104.25 C612.1 68.22,103.8 67.4,102.97 U601.7
VDDC_ENB: length 27.6
  TOP w0.1: Q4010.1 71.52,107.54 C4401.1 72.15,106.8 v3(72.65,106.3) 72.65,106.1 72.15,105.6 R4053.1 ; v3(87.5,106.3) 87.5,99.18 R4051.1
  BOTTOM w0.1: v3(87.5,106.3) 74.35,106.3 73.75,106.9 73.25,106.9 v3(72.65,106.3)
VDDC_FB: length 9.6
  TOP w0.5: R4078.2 R1226.1 R1225.1 68.35,98.9 68.96,99.51 R611.1 R613.1 R610.2 R614.1 68.66,102.8 67.56,101.7 U601.6
VDDC_FB_IN1: length 12.6
  TOP w0.1: R1226.2 v3(69.35,96.3)
  BOTTOM w0.1: Q1200.3 70.49,103.16 69.35,102.02 v3(69.35,96.3)
VDDC_FB_IN2: length 21.3
  TOP w0.1: R1225.2 v3(68.35,96.3)
  BOTTOM w0.1: v3(68.35,96.3) 68.35,108.5 69.45,109.6 73.45,109.6 74.49,108.56 Q1201.3
VDDC_FB_TRACE: length 69.1
  TOP w0.1: v3(65.65,85) 68.35,87.7 70.75,87.7 71.55,88.5 R600.1
  L3_INNER w0.1: NS600.2 87.14,56.11 86.65,56.6 85.85,56.6 85.55,56.9 85.55,58 85.33,58.22 83.69,58.22 83.59,58.12 82.14,58.12 81.62,57.61 81.15,57.61 79.93,56.4 74.2,56.4 68.42,62.18 67.55,62.18 64.33,65.4 61.7,65.4 60.28,66.82 v3(60.28,67.5)
  BOTTOM w0.1: v3(65.65,85) 65.04,84.39 65.04,79.81 60.28,75.05 v3(60.28,67.5)
